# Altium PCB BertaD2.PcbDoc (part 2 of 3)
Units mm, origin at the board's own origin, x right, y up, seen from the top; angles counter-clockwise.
Board outline 100.5 x 100 mm, 4 copper layers (Top Layer, Signal Layer 1, Signal Layer 2, Bottom Layer), stack 0.778 mm thick; 108 components, 216 nets, 850 pads, 807 vias.
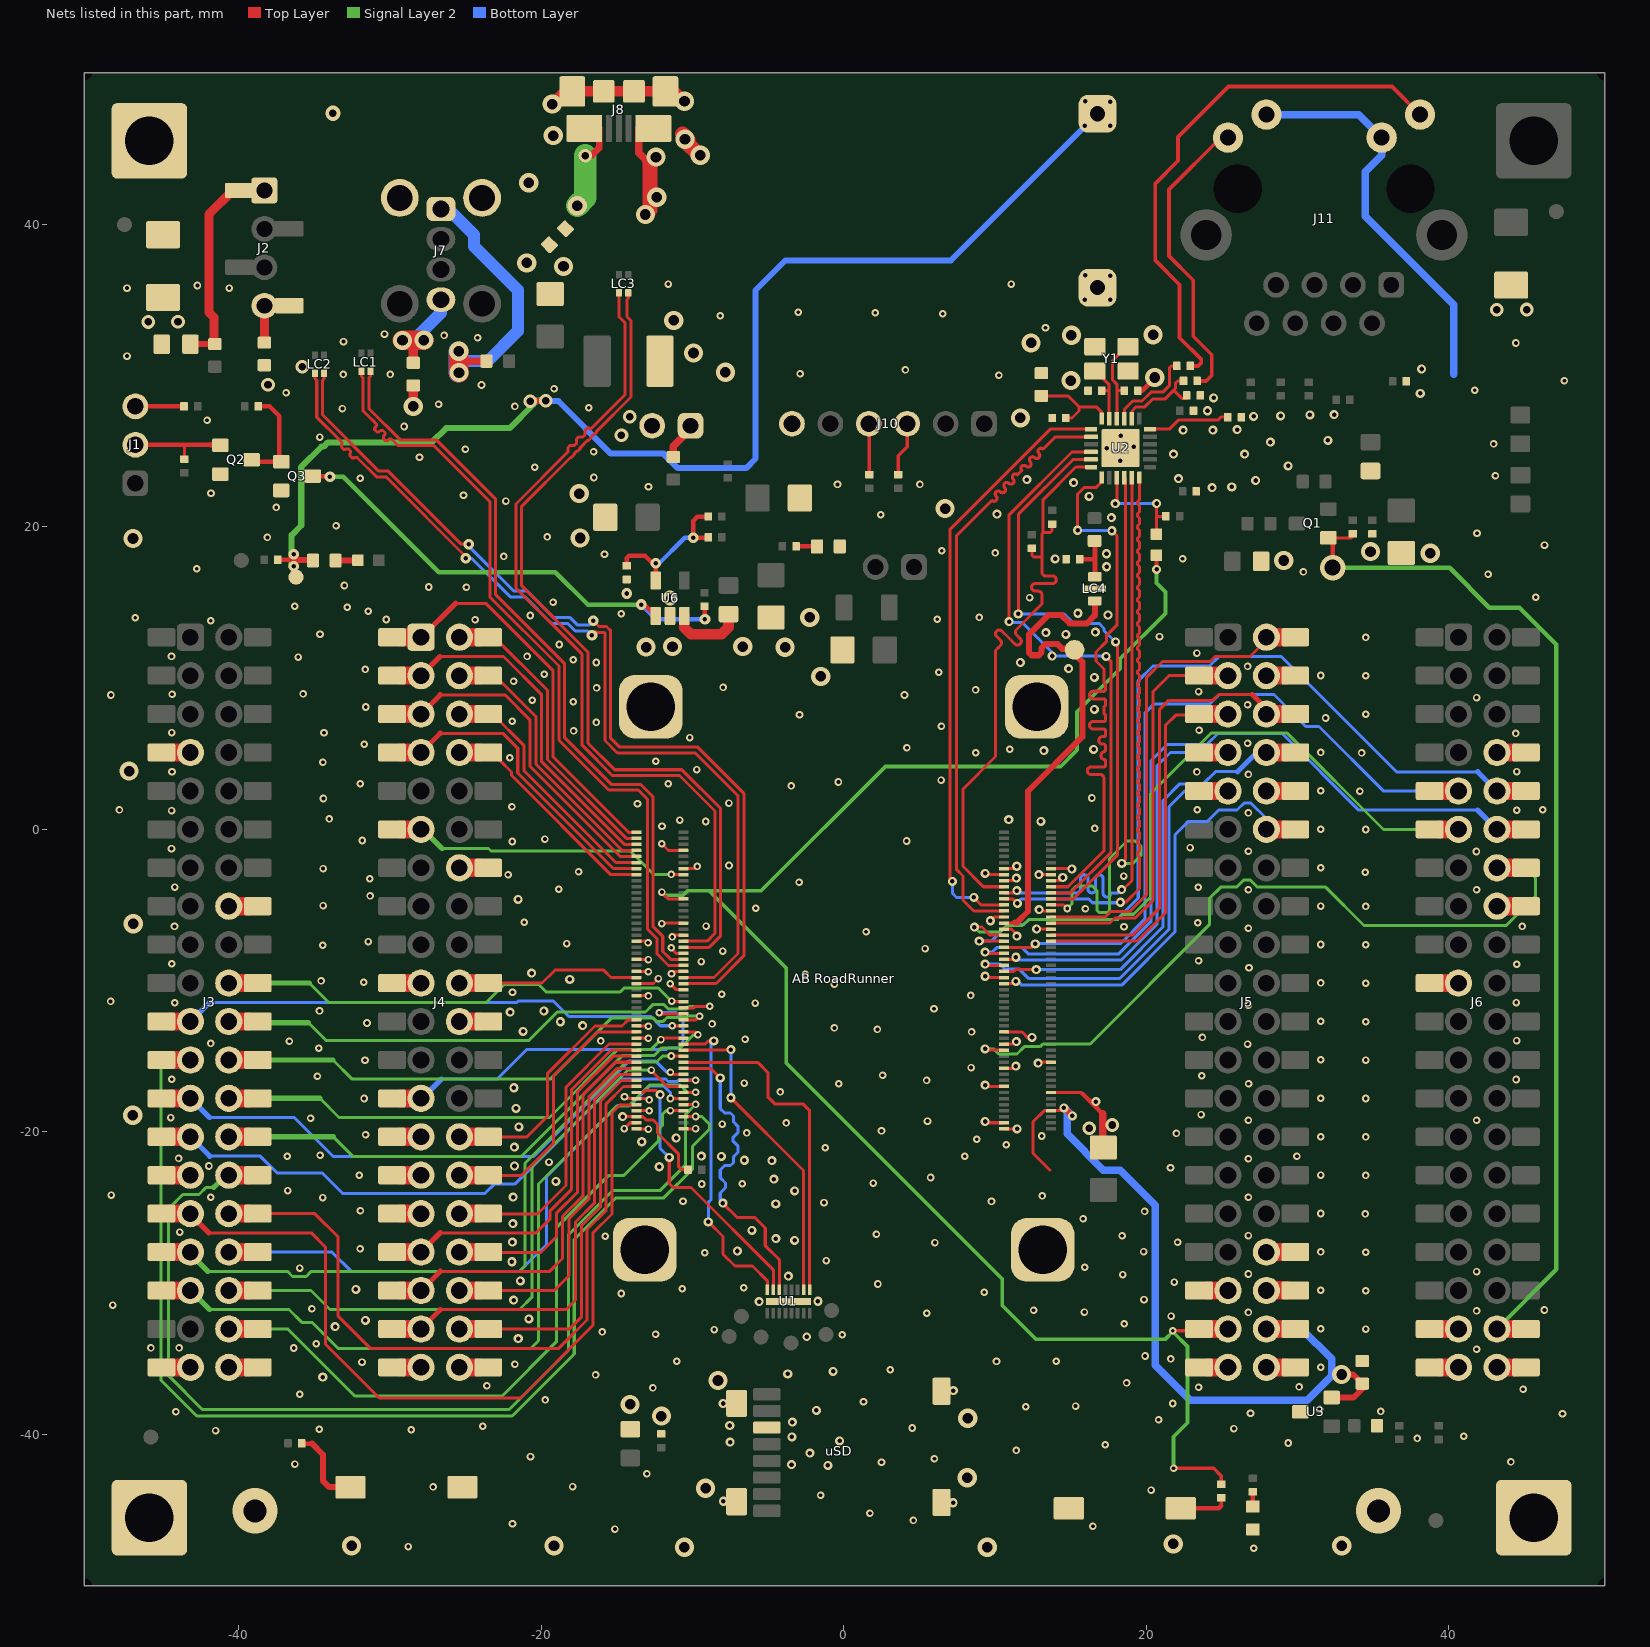
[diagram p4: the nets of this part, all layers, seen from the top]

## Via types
v1: diameter 0.5, hole 0.25, Top Layer to Bottom Layer, tented both sides, 469 vias
v2: diameter 0.6, hole 0.3, Top Layer to Bottom Layer, tented both sides, 200 vias
v3: diameter 1.27, hole 0.7, Top Layer to Bottom Layer, tented both sides, 72 vias
v4: diameter 0.7, hole 0.3, Top Layer to Bottom Layer, tented both sides, 20 vias
v5: diameter 0.9, hole 0.5, Top Layer to Bottom Layer, tented both sides, 19 vias
v6: diameter 0.7, hole 0.3, Top Layer to Bottom Layer, 8 vias
v7: diameter 1, hole 0.5, Top Layer to Bottom Layer, tented both sides, 6 vias
v8: diameter 1.7, hole 1.05, Top Layer to Bottom Layer, tented both sides, 5 vias
v9: diameter 3, hole 1.5, Top Layer to Bottom Layer, 3 vias
v10: diameter 1.7, hole 1.05, Top Layer to Bottom Layer, 3 vias
v11: diameter 0.56, hole 0.3, Top Layer to Bottom Layer, tented both sides, 1 vias
v12: diameter 0.8, hole 0.4, Top Layer to Bottom Layer, tented both sides, 1 vias

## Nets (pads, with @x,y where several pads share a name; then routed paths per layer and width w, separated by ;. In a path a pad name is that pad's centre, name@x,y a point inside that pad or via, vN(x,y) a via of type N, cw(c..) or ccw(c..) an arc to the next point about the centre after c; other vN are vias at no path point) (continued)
EARTH2: C6.2 J7.5 J7.6 J8.6 J8.7 J8.8 J8.9 J8.10 J8.11 pad.8@-45.892,45.508 | length 11.6
  Top Layer w0.7: v3(-19.26,47.94) -18.42,48.78 J8.10@-17.935,48.78 J8.9@-15.86,48.78 J8.8@-13.86,48.78 J8.7@-11.785,48.78 -11.17,48.78 v3(-10.52,48.13)
  Top Layer w1: v3@-10.653,45.968 -10.393,45.708 -10.295,45.61 v3(-10.49,45.61) -10.49,45.51 -9.54,44.56 v3(-9.48,44.56)
  other v3: -20.82,42.74 -19.2,45.86
  other v7: -33.76,47.33
ECK: C21.1 L9.1 LC4.1 | length 3.5
  Top Layer w0.3: C21.1@15.6,17.86 16.61,17.86 ; L9.1@16.54,19.12 16.585,19.075 16.61,19.05 16.61,17.86 ; LC4.1@16.57,16.71 16.58,16.72 16.61,16.75 16.61,17.86 ; 16.63,17.85 16.62,17.86 16.61,17.86
EN33: Q3.3 R4.2 U6.1 | length 32.1
  Top Layer w0.3: Q3.3@-35.232,23.353 -35.1,23.353 -33.999,23.353 v4(-33.957,23.311) ; v4(-13.376,14.862) -13.178,14.862 U6.1@-12.43,14.114 ; v4@-9.177,13.884 R4.2@-9.177,14.698
  Signal Layer 2 w0.3: v4(-33.957,23.311) -33.073,23.311 -26.76,16.998 -19.063,16.998 -16.927,14.862 v4(-13.376,14.862)
  Bottom Layer w0.3: v4(-13.376,14.862) -12.391,13.877 v4(-9.17,13.877)
ENABLE_ETH_N: J6.38 Q1.1 R11.2 | length 68.4
  Top Layer w0.2: Q1.1@32.32,18.98 Q1.1@32.03,19.27 33.55,19.27 33.65,19.37 R11.2@33.65,19.54
  Top Layer w0.3: v10@31.66,17.33 31.69,17.3 v10(32.32,17.3) Q1.1@32.32,18.98
  Signal Layer 2 w0.3: v10(32.32,17.3) 32.335,17.285 40.055,17.285 42.68,14.66 44.67,14.66 47.11,12.22 47.11,-29.09 J6.38@43.18,-33.02
ETH_CLK: "25 MHz.1" "AB RoadRunner.J2-31" LC4.2 | length 32
  Top Layer w0.2: 10.591,-6.191 10.595,-6.191 11.354,-6.19
  Top Layer w0.4: 11.327,-6.141 11.47,-6.141 12.18,-5.431 12.18,2.52 15.77,6.11 15.77,11.07 15.115,11.725 14.9,11.94 14.44,11.94 14.12,12.26 13.35,12.26 13.07,11.98 13.07,11.68 12.9,11.51 12.42,11.51 12.26,11.67 12.26,12.9 13.52,14.16 14.38,14.16 14.933,13.607 16.067,13.607 16.6,14.14 LC4.2@16.6,15.1
ETH_CRS: "AB RoadRunner.J2-24" U2.11 | length 39.8
  Top Layer w0.2: v2@11.54,14.28 11.54,20.82 15.17,24.45 U2.11@16.35,24.45 ; 13.705,-4.593 15.192,-4.593 18.112,-1.673 18.112,12.198 v2@17.96,12.35
  Bottom Layer w0.2: v2(11.54,14.24) 14.57,14.24 15.19,13.62 16.87,13.62 17.21,13.28 17.21,13.13 17.96,12.38 v2(17.97,12.39)
ETH_MDC: "AB RoadRunner.J2-20" U2.13 | length 40.1
  Top Layer w0.2: 13.705,-3.792 14.821,-3.792 17.2,-1.413 17.2,3.25 17.2,3.38 ccw(c16.95,3.38) 16.95,3.63 16.35,3.63 cw(c16.35,3.88) 16.1,3.88 cw(c16.35,3.88) 16.35,4.13 17.2,4.13 ccw(c17.2,4.232) 17.302,4.232 17.302,4.528 ccw(c17.2,4.528) 17.2,4.63 cw(c17.2,4.809) 17.021,4.809 17.021,4.951 cw(c17.2,4.951) 17.2,5.13 ccw(c17.2,5.232) 17.302,5.232 17.302,5.528 ccw(c17.2,5.528) 17.2,5.63 17.108,5.63 cw(c17.108,5.88) 16.858,5.88 cw(c17.108,5.88) 17.108,6.13 17.2,6.13 ccw(c17.2,6.232) 17.302,6.232 17.302,6.528 ccw(c17.2,6.528) 17.2,6.63 16.5,6.63 cw(c16.5,6.88) 16.25,6.88 cw(c16.5,6.88) 16.5,7.13 17.2,7.13 ccw(c17.2,7.232) 17.302,7.232 17.302,7.528 ccw(c17.2,7.528) 17.2,7.63 17.2,8.13 ccw(c17.2,8.232) 17.302,8.232 17.302,8.528 ccw(c17.2,8.528) 17.2,8.63 16.5,8.63 cw(c16.5,8.88) 16.25,8.88 cw(c16.5,8.88) 16.5,9.13 17.2,9.13 ccw(c17.2,9.232) 17.302,9.232 17.302,9.528 ccw(c17.2,9.528) 17.2,9.63 17.2,9.88 17.2,10.606 16.675,11.131 16.675,11.719 17.36,12.404 17.36,12.8 18.08,13.52 18.08,19.39 v2(17.73,19.74) ; v2(15.46,19.77) 15.46,22.16 15.912,22.612 16.702,22.612 17.05,22.96 U2.13@17.05,23.25
  Bottom Layer w0.2: v2(15.46,19.77) 17.7,19.77 v2(17.73,19.74)
ETH_MDIO: "AB RoadRunner.J2-19" R13.2 R14.2 U2.12 | length 41.4
  Top Layer w0.2: 10.595,-3.792 9.232,-3.792 7.885,-2.445 7.885,2.655 10.04,4.81 10.04,11.83 10.135,11.925 10.183,11.973 10.359,12.149 ccw(c10.183,12.326) 10.359,12.503 10.112,12.75 cw(c10.289,12.927) 10.112,13.104 cw(c10.289,12.927) 10.465,13.104 10.89,12.68 11.314,12.255 ccw(c11.491,12.432) 11.667,12.255 ccw(c11.491,12.432) 11.667,12.609 11.42,12.856 cw(c11.597,13.033) 11.42,13.21 13.1,14.89 13.1,15.49 13.1,15.5 ccw(c12.85,15.5) 12.85,15.75 12.672,15.75 cw(c12.672,16) 12.422,16 cw(c12.672,16) 12.672,16.25 13.1,16.25 13.8,16.25 ccw(c13.8,16.5) 14.05,16.5 ccw(c13.8,16.5) 13.8,16.75 13.35,16.75 cw(c13.35,17) 13.1,17 13.1,18 ; R13.2@12.44,18.57 12.44,18.12 12.56,18 13.1,18 ; 13.184,19.61 13.184,21.79 15.344,23.95 U2.12@16.35,23.95 ; R14.2@13.77,20.18 13.77,19.74 13.64,19.61 13.208,19.61 13.1,19.502 13.1,18
ETH_RX0: "AB RoadRunner.J2-27" U2.8 | length 41.4
  Top Layer w0.2: 10.595,-5.392 8.608,-5.392 8.6,-5.4 7.88,-4.68 7.88,-3.08 7.471,-2.671 7.471,19.421 9.69,21.64 9.792,21.742 ccw(c9.933,21.883) 10.074,21.742 ccw(c9.933,21.883) 10.074,22.024 cw(c10.216,22.166) 10.074,22.307 cw(c10.216,22.166) 10.357,22.307 ccw(c10.499,22.449) 10.64,22.307 ccw(c10.499,22.449) 10.64,22.59 cw(c10.782,22.732) 10.64,22.873 cw(c10.782,22.732) 10.923,22.873 ccw(c11.064,23.014) 11.206,22.873 ccw(c11.064,23.014) 11.206,23.156 cw(c11.347,23.297) 11.206,23.439 cw(c11.347,23.297) 11.489,23.439 11.772,23.722 cw(c11.913,23.863) 11.772,24.004 cw(c11.913,23.863) 12.054,24.004 ccw(c12.196,24.146) 12.337,24.004 ccw(c12.196,24.146) 12.337,24.287 cw(c12.479,24.429) 12.337,24.57 cw(c12.479,24.429) 12.62,24.57 ccw(c12.761,24.711) 12.903,24.57 ccw(c12.761,24.711) 12.903,24.853 cw(c13.044,24.994) 12.903,25.136 cw(c13.044,24.994) 13.186,25.136 13.469,25.419 13.61,25.56 14,25.95 U2.8@16.35,25.95
ETH_RX1: "AB RoadRunner.J2-25" U2.7 | length 39.9
  Top Layer w0.2: v2(7.19,-3.44) 7.038,-3.288 7.038,19.838 13.65,26.45 U2.7@16.35,26.45 ; v2(8.6,-4.5) 9.092,-4.992 10.595,-4.992
  Bottom Layer w0.2: v2(7.19,-3.44) 7.19,-4.23 7.46,-4.5 v2(8.6,-4.5)
ETH_RXER: "AB RoadRunner.J2-22" U2.10 | length 39.9
  Top Layer w0.2: v2(10.94,13.73) 10.94,20.8 15.09,24.95 U2.10@16.35,24.95 ; 13.705,-4.192 14.999,-4.192 17.682,-1.509 17.682,11.088 v2(17.34,11.43)
  Bottom Layer w0.2: v2(10.94,13.73) 11.01,13.66 11.82,13.66 13.77,11.71 v2(13.77,11.46) 17.31,11.46 v2(17.34,11.43)
ETH_TX0: "AB RoadRunner.J2-21" U2.17 | length 39.9
  Top Layer w0.2: 10.595,-4.192 11.308,-4.192 v2(11.45,-4.05) ; v2(18.37,-3.98) 18.457,-3.98 19.05,-3.387 U2.17@19.05,23.25
  Bottom Layer w0.2: v2(11.45,-4.05) 11.6,-4.2 14.92,-4.2 15.15,-4.2 15.4,-4.2 ccw(c15.4,-3.95) 15.65,-3.95 15.65,-3.25 cw(c15.9,-3.25) 15.9,-3 cw(c15.9,-3.25) 16.15,-3.25 16.15,-3.95 ccw(c16.4,-3.95) 16.4,-4.2 ccw(c16.4,-3.95) 16.65,-3.95 16.65,-3.25 cw(c16.9,-3.25) 16.9,-3 cw(c16.9,-3.25) 17.15,-3.25 17.15,-4.2 17.15,-4.22 ccw(c17.4,-4.22) 17.4,-4.47 ccw(c17.4,-4.22) 17.65,-4.22 cw(c17.67,-4.22) 17.67,-4.2 17.9,-4.2 18.15,-4.2 v2(18.37,-3.98)
ETH_TX1: "AB RoadRunner.J2-23" U2.18 | length 39.8
  Top Layer w0.2: 10.595,-4.593 11.172,-4.593 v2@11.43,-4.85 ; v2(18.288,-4.815) 18.645,-4.815 19.55,-3.91 19.55,-2.4 19.55,-2.22 19.55,-1.82 19.43,-1.7 19.43,-1.54 19.55,-1.42 19.55,-1.02 19.43,-0.9 19.43,-0.74 19.55,-0.62 19.55,-0.22 19.43,-0.1 19.43,0.06 19.55,0.18 19.55,0.58 19.43,0.7 19.43,0.86 19.55,0.98 19.55,1.38 19.43,1.5 19.43,1.66 19.55,1.78 19.55,2.18 19.43,2.3 19.43,2.46 19.55,2.58 19.55,2.98 19.43,3.1 19.43,3.26 19.55,3.38 19.55,3.78 19.43,3.9 19.43,4.06 19.55,4.18 19.55,4.58 19.43,4.7 19.43,4.86 19.55,4.98 19.55,5.38 19.43,5.5 19.43,5.66 19.55,5.78 19.55,6.18 19.43,6.3 19.43,6.46 19.55,6.58 19.55,6.98 19.43,7.1 19.43,7.26 19.55,7.38 19.55,7.78 19.43,7.9 19.43,8.06 19.55,8.18 19.55,8.58 19.43,8.7 19.43,8.86 19.55,8.98 19.55,9.38 19.43,9.5 19.43,9.66 19.55,9.78 19.55,10.18 19.43,10.3 19.43,10.46 19.55,10.58 19.55,10.98 19.43,11.1 19.43,11.26 19.55,11.38 19.55,11.78 19.43,11.9 19.43,12.06 19.55,12.18 19.55,12.58 19.43,12.7 19.43,12.86 19.55,12.98 19.55,13.38 19.43,13.5 19.43,13.66 19.55,13.78 19.55,14.18 19.43,14.3 19.43,14.46 19.55,14.58 19.55,14.98 19.43,15.1 19.43,15.26 19.55,15.38 19.55,15.78 19.43,15.9 19.43,16.06 19.55,16.18 19.55,16.58 19.43,16.7 19.43,16.86 19.55,16.98 19.55,17.38 19.43,17.5 19.43,17.66 19.55,17.78 19.55,18.18 19.43,18.3 19.43,18.46 19.55,18.58 19.55,18.98 19.43,19.1 19.43,19.26 19.55,19.38 19.55,19.78 19.43,19.9 19.43,20.06 19.55,20.18 19.55,20.58 19.43,20.7 19.43,20.86 19.55,20.98 19.55,21.38 19.43,21.5 19.43,21.66 19.55,21.78 19.55,22.18 19.55,22.38 U2.18@19.55,23.25
  Bottom Layer w0.2: v2(11.477,-4.896) 11.477,-4.867 11.498,-4.846 11.476,-4.824 11.67,-4.63 11.69,-4.63 11.72,-4.6 16.195,-4.6 16.445,-4.85 18.26,-4.85 18.288,-4.822 v2(18.288,-4.815)
ETH_TXEN: "AB RoadRunner.J2-26" U2.16 | length 40.5
  Top Layer w0.2: 13.705,-4.992 14.543,-4.992 v1(14.78,-5.23) ; v2(18.38,-2.25) 18.625,-2.005 18.625,23.175 U2.16@18.55,23.25
  Signal Layer 2 w0.2: v1(14.78,-5.23) 15.09,-4.92 15.09,-4.03 15.38,-3.74 16.43,-3.74 16.74,-4.05 16.74,-5.35 16.87,-5.48 17.45,-5.48 17.57,-5.36 17.57,-1.92 18.72,-0.77 19.28,-0.77 19.66,-1.15 19.66,-1.69 19.1,-2.25 v2(18.38,-2.25)
ETHLED1: J11.9 R20.2 | length 35.8
  Top Layer w0.25: R20.2@22.92,30.63 23.41,30.63 23.64,30.86 23.64,31.06 22.2,32.5 22.2,36 20.6,37.6 20.6,42.7 22.1,44.2 22.1,45.763 25.437,49.1 36.24,49.1 J11.9@38.1,47.24
ETHLED2: J11.12 R21.2 | length 19.9
  Top Layer w0.25: R21.2@23.36,29.64 23.97,29.64 24.33,30 24.33,31.37 23.1,32.6 23.1,36.3 21.5,37.9 21.5,42.3 24.92,45.72 J11.12@25.4,45.72
FUSE2V5: "AB RoadRunner.J2-94" C27.1 J5.38 U3.2 | length 51.5
  Top Layer w0.2: 13.64,-22.53 12.513,-21.403 12.513,-19.328 13.248,-18.593 13.705,-18.593 14.554,-18.593 14.773,-18.593 14.81,-18.593 ; v2@14.526,-18.404 v2(14.554,-18.404)
  Top Layer w0.4: v2(14.554,-18.404) 14.584,-18.404 14.773,-18.593 v2(15.12,-18.94) ; U3.2@32.25,-37.55 33.7,-37.55 34.28,-36.97 C27.1@34.28,-36.64 33.67,-36.03 v3(32.91,-36.03)
  Bottom Layer w0.5: v2(14.554,-18.404) 14.584,-18.404 v2@14.77,-18.59 ; v2(15.12,-18.94) v2@14.77,-18.59 ; J5.38@27.94,-33.032 30.292,-33.032 32.25,-34.99 32.25,-36.03 32.25,-36.12 30.63,-37.74 22.92,-37.74 20.6,-35.42 20.6,-24.86 18.27,-22.53 17.17,-22.53 14.77,-20.13 14.77,-18.94 v2@14.77,-18.59
GND: "AB RoadRunner.J1-8" "AB RoadRunner.J1-14" "AB RoadRunner.J1-32" "AB RoadRunner.J1-36" "AB RoadRunner.J1-37" "AB RoadRunner.J1-42" "AB RoadRunner.J1-43" "AB RoadRunner.J1-47" "AB RoadRunner.J1-48" "AB RoadRunner.J1-51" "AB RoadRunner.J1-54" "AB RoadRunner.J1-55" "AB RoadRunner.J1-65" "AB RoadRunner.J1-69" "AB RoadRunner.J1-89" "AB RoadRunner.J1-93" "AB RoadRunner.J1-97" "AB RoadRunner.J1-99" "AB RoadRunner.J1-100" "AB RoadRunner.J1-101" "AB RoadRunner.J1-102" "AB RoadRunner.J2-13" "AB RoadRunner.J2-14" "AB RoadRunner.J2-15" "AB RoadRunner.J2-16" "AB RoadRunner.J2-17" "AB RoadRunner.J2-18" "AB RoadRunner.J2-28" "AB RoadRunner.J2-29" "AB RoadRunner.J2-33" "AB RoadRunner.J2-34" "AB RoadRunner.J2-49" "AB RoadRunner.J2-67" "AB RoadRunner.J2-71" "AB RoadRunner.J2-78" "AB RoadRunner.J2-79" "AB RoadRunner.J2-85" "AB RoadRunner.J2-88" "AB RoadRunner.J2-97" "AB RoadRunner.J2-99" "AB RoadRunner.J2-101" "AB RoadRunner.J2-102" C1.2 C2.2 C3.2 C4.2 C6.1 C7.2 C8.2 C9.1 C10.2 C11.2 C12.2 C13.2 C14.2 C15.1 C16.1 C17.2 C18.2 C19.2 C20.2 C21.2 C22.2 C23.2 C24.2 C25.2 C26.1 C27.2 DL1.K DL2.K J3.7 J3.16 J3.29 J3.39 J3.40 J4.14 J4.19 J4.22 J4.29 J4.39 J4.40 J5.4 J5.10 J5.36 J5.39 J5.40 J6.8 J6.16 J6.19 J6.39 J6.40 J9.2 J10.6 J11.10 J11.11 L4.1 L5.1 L6.1 LC4.3 P1.1 P2.1 pad.8@45.608,-45.492 pad.8@-45.892,-45.492 Q2.2 Q3.2 R5.2 R22.1 R23.2 U1.17 U2.25 U3.3 U6.2 uSD.6 uSD.9 uSD.10 uSD.11 uSD.12 Y1.2 Y1.4 | length 80.6
  Top Layer w0.2: J4.22@-25.59,-12.85 -25.42,-12.68 J4.22@-25.37,-12.63 ; v1(-14.5,-19.775) -14.117,-19.392 -13.705,-19.392 ; v1(-14.49,-17.68) -14.377,-17.792 -13.705,-17.792 v1@-12.852,-17.792 ; -13.928,-10.192 -13.705,-10.192 -12.572,-10.192 v1(-12.244,-9.864) ; -13.888,-10.993 -13.705,-10.993 v1@-12.91,-10.993 ; -13.705,-19.793 -12.91,-19.793 v1@-12.852,-19.793 ; -13.705,-18.593 v1(-12.852,-18.593) ; -13.705,-13.792 -12.91,-13.792 v1@-12.852,-13.792 ; -13.705,-12.992 -12.91,-12.992 v1@-12.852,-12.992 ; -13.705,-9.393 -12.91,-9.393 v1@-12.852,-9.393 ; -13.705,-8.592 -12.91,-8.592 v1@-12.852,-8.592 ; -13.705,-7.392 -12.93,-7.392 v1@-12.852,-7.392 ; v1@-12.03,-6.192 -12.021,-6.192 -10.595,-6.192 ; v1(-12.02,-0.95) -11.578,-1.392 -10.595,-1.392 ; v1(-11.47,-10.2) -11.46,-10.2 -11.068,-10.592 ; v1@-11.447,-9.393 -11.38,-9.393 -10.595,-9.393 ; v1(-11.403,-7.829) -11.403,-7.877 -11.087,-8.193 ; v1(-11.334,-7.106) -11.326,-7.106 v1@-11.212,-6.993 ; v1@-11.209,-6.993 -10.595,-6.993 ; -11.045,-10.592 -10.595,-10.592 ; -11.045,-8.193 -10.595,-8.193 ; -10.595,-19.793 -9.79,-19.793 v1@-9.742,-19.793 ; -10.595,-2.592 v1@-9.742,-2.592 ; v2(9.35,-19.31) 9.432,-19.392 10.595,-19.392 ; v2(9.35,-16.91) 9.432,-16.993 10.595,-16.993 ; v2(9.35,-9.71) 9.432,-9.793 10.595,-9.793 ; v2(9.35,-2.91) 9.432,-2.992 10.595,-2.992 ; v2(9.697,-6.038) 9.944,-5.791 10.593,-5.791 ; 10.595,-19.793 11.459,-19.793 11.519,-19.793 11.517,-19.794 v2(11.459,-19.794) ; 10.595,-15.793 11.238,-15.793 v2(11.38,-15.65) ; 10.595,-14.193 v2@11.238,-14.193 ; 10.595,-3.393 11.258,-3.393 11.414,-3.236 v2(11.414,-3.225) ; 10.595,-2.592 11.388,-2.592 11.44,-2.54 v2(11.44,-2.436) ; 10.629,-13.394 11.794,-13.394 v2@12.2,-13.8 ; 10.629,-6.593 11.093,-6.593 v2@11.47,-6.97 ; v2@12.75,-15.391 12.856,-15.391 13.705,-15.391 ; v2(12.75,-6.585) 12.757,-6.592 13.705,-6.592 ; v2@12.902,-2.992 13.705,-2.992 ; v2@12.992,-5.392 13.705,-5.392 ; 13.705,-17.392 15.713,-17.392 ; 13.705,-3.393 14.268,-3.393 v2(14.48,-3.18) ; 13.705,-2.592 v2@15.08,-2.592
  Top Layer w0.25: C10.2@17.13,-20.99 C10.2@17.17,-21.03
  Top Layer w0.3: 15.818,-17.498 16.495,-18.175 17.13,-18.81 ; C20.2@19.45,29 19.731,29 20.56,29.829 v3(20.56,29.87)
  Top Layer w0.5: C10.2@17.13,-20.99 17.13,-19.54 17.13,-18.81
  Top Layer w0.6: v3(-28.45,27.96) L4.1@-28.45,29.34 ; v6(15.946,35.007) 15.982,35.007 C7.2@16.78,35.805 ; v6(15.978,36.633) 15.978,36.607 C7.2@16.78,35.805 ; v6(17.604,35.007) 17.578,35.007 C7.2@16.78,35.805 ; v6(17.604,36.601) 17.576,36.601 C7.2@16.78,35.805
  Top Layer w1.2: J5.36@27.94,-30.48 27.958,-30.462 29.222,-30.462 J5.36@29.24,-30.48
  Bottom Layer w0.5: J11.11@27.94,47.24 34.04,47.24 J11.10@35.56,45.72 35.56,44.55 34.48,43.47 34.48,40.54 40.33,34.69 40.33,30.08
  other v1: 27.11,-47.52 -28.78,-47.41 -15.12,-46.25 16.47,-46.06 -21.89,-45.89 4.61,-45.68 1.73,-45.21 -1.53,-44.02 20.32,-43.67 -27.14,-43.46 -17.92,-43.44 -13.01,-42.59 -36.27,-41.95 2.5,-41.83 44.1,-41.81 6,-41.6 -20.7,-41.46 11.4,-41.05 17.29,-40.67 29.38,-40.56 37.91,-40.26 40.99,-40.11 -41.52,-39.74 -28.58,-39.69 -34.67,-39.65 25.793,-39.61 4.53,-39.57 -23.86,-39.45 20.813,-39.029 47.51,-38.63 26.89,-38.59 -44.142,-38.497 35.5,-38.47 31.46,-38.32 12.04,-38.16 15.33,-38.12 21.75,-37.95 1.31,-37.83 -19.73,-37.71 -35.95,-37.34 44.904,-37 -12.61,-36.92 23.46,-36.87 30.1,-36.85 -23.58,-36.77 18.7,-36.59 -16.4,-36.06 3.08,-35.72 31.53,-35.55 -21.73,-35.358 -31.84,-35.21 -11.03,-35.16 10.1,-35.17 14.05,-35.15 21.62,-35 19.92,-34.81 41.83,-34.36 -45.793,-34.272 -43.929,-34.274 -36.35,-34.28 -34.87,-34 -0.1,-33.4 -12.43,-33.37 -15.96,-33.22 -8.55,-33.06 34.51,-33.03 31.53,-33.01 18.54,-32.68 21.64,-32.17 5.49,-31.98 26.75,-31.93 15.91,-31.91 41.83,-31.83 12.55,-31.78 46.319,-31.767 -35.149,-31.682 -48.309,-31.441 19.85,-31.08 -14.7,-30.68 9.29,-30.6 34.51,-30.49 31.53,-30.47 -10.67,-30.36 -6.61,-30.3 2.26,-30.05 21.85,-29.92 18.44,-29.43 26.75,-29.39 41.83,-29.23 -35.96,-29 15.94,-28.95 -1.16,-28.5 -9.19,-27.98 34.51,-27.95 19.82,-27.91 31.53,-27.93 -31.962,-27.722 6.03,-27.31 22.07,-27.29 -15.76,-26.9 18.4,-26.86 26.75,-26.85 2.16,-26.76 -43.89,-26.62 15.82,-25.74 34.48,-25.416 31.53,-25.39 19.89,-25.25 -31.943,-25.213 -1.3,-24.67 -10.62,-24.58 9.77,-24.59 -34.43,-24.34 -41.83,-24.31 26.75,-24.31 13.12,-24.23 -48.406,-24.173 -36.744,-23.878 -9.38,-23.44 -6.7,-23.43 1.95,-23.38 5.74,-23.01 -32.02,-22.86 34.51,-22.87 31.53,-22.85 21.6,-22.37 -41.96,-22.25 -19.48,-21.99 26.75,-21.77 -43.96,-21.75 -36.78,-21.61 8,-21.61 29.96,-21.61 -34.61,-21.54 -1.22,-21.04 10.75,-20.841 8.8,-20.48 34.51,-20.33 31.53,-20.31 13.093,-20.269 -31.6,-20.19 21.99,-20.1 -6.41,-20.06 2.5,-19.93 -12.91,-19.81 -9.79,-19.78 -8.03,-19.48 -3.8,-19.4 5.54,-19.28 26.75,-19.23 41.83,-19.23 -35.24,-19.09 -44.483,-19.054 23.62,-18.85 -12.852,-17.883 -31.7,-17.79 34.51,-17.79 31.53,-17.77 -4.2,-17.35 -0.32,-16.82 26.764,-16.811 -6.57,-16.77 5.48,-16.59 44.443,-16.532 -44.414,-16.523 -34.785,-16.325 23.66,-16.289 2.57,-16.25 8.421,-15.744 -31.64,-15.26 34.51,-15.25 31.53,-15.23 -34.7,-14.47 26.7,-14.19 -41.83,-14.15 -36.64,-14.01 -16.06,-13.98 44.474,-13.962 -6.519,-13.867 -12.91,-13.81 23.71,-13.75 8.45,-13.386 2.23,-13.22 -0.61,-13.12 -12.91,-13.01 -8.7,-12.862 -31.51,-12.8 34.51,-12.71 31.53,-12.69 -34.65,-12 5.97,-11.86 26.75,-11.61 -5.85,-11.48 -44.216,-11.457 44.451,-11.447 -48.454,-11.371 -12.91,-11.01 8.398,-10.972 -8.053,-10.891 -21.89,-10.77 -0.61,-10.22 34.51,-10.17 31.53,-10.15 -31.73,-10.1 -34.54,-10.02 -2.54,-9.58 -11.38,-9.542 -12.91,-9.41 26.791,-9.149 44.487,-8.915 -44.418,-8.884 -9.41,-8.74 23.46,-8.69 -12.91,-8.61 -7.994,-8.048 5.38,-7.88 -34.44,-7.66 34.51,-7.63 31.53,-7.61 -18.3,-7.55 -12.93,-7.487 -31.42,-7.42 1.48,-6.76 26.75,-6.53 18.529,-6.439 -44.234,-6.416 44.845,-6.411 -9.093,-6.391 -12.021,-6.23 23.4,-6.17 -21.11,-6.14 15.98,-5.24 -5.81,-5.21 34.51,-5.09 31.53,-5.07 -34.41,-5.04 -31.308,-4.396 26.75,-3.99 41.83,-3.99 -18.841,-3.962 23.43,-3.83 -44.221,-3.813 -2.95,-3.5 -31.323,-3.259 18.51,-3.09 -22.184,-3.001 34.479,-2.836 -17.524,-2.808 -34.41,-2.59 31.53,-2.53 -9.68,-2.45 -7.58,-2.39 26.75,-1.45 41.818,-1.462 -44.43,-1.268 22.896,-1.203 -21.907,-0.803 4.16,-0.77 -31.821,-0.734 -19.752,-0.642 34.51,-0.01 31.53,0.01 16.599,0.066 -12.01,0.21 -9.118,0.519 -10.842,0.613 -34.003,0.688 26.75,1.09 -44.428,1.243 44.485,1.269 -47.873,1.289 23.37,1.29 46.207,1.29 -21.928,1.494 -13.63,1.69 -7.59,1.74 -34.39,2.04 16.406,2.075 34.12,2.52 31.53,2.55 -3.46,2.87 -31.95,3.01 -11.6,3.01 -0.35,3.13 6.44,3.26 26.75,3.63 -44.396,3.812 23.35,3.8 44.49,3.819 -9.71,3.95 -34.42,4.43 -12.426,4.5 -22.077,4.741 8.73,5.06 34.233,5.053 31.53,5.09 10.97,5.3 4.18,5.4 -31.69,5.63 26.7,5.69 -10.17,6.07 44.427,6.344 -34.35,6.38 -44.416,6.394 -17.851,6.506 23.492,6.557 6.46,6.81 -16.36,7.07 -21.91,7.15 31.85,7.36 -2.92,7.57 34.51,7.61 -31.59,8.09 26.7,8.23 -17.87,8.44 -20.59,8.54 41.83,8.71 -48.437,8.882 4.02,8.88 -44.395,8.925 -35.73,8.95 23.46,9.11 8.72,9.22 -16.33,9.35 -7.97,9.38 -21.82,9.79 34.51,10.15 31.53,10.17 -19.79,10.26 6.28,10.39 -31.62,10.57 26.7,10.77 -16.35,11.03 -17.87,11.21 -36.05,11.39 -44.431,11.429 -20.93,11.43 23.344,11.649 -18.8,12.22 34.51,12.69 20.875,12.744 -34.616,12.899 -41.83,13.79 -30.24,13.871 -24.361,13.858 6.18,13.89 -46.82,13.99 8.96,14.01 -20.713,14.138 -14.7,14.25 -31.43,14.42 -32.81,14.68 -36.28,14.75 -19.21,15.016 12.29,15.32 45.746,15.338 -27.43,16.02 -24.94,16.01 -33,16.12 42.59,16.87 30.39,17.02 -42.76,17.22 22.4,17.89 -22.466,18.04 -15.81,18.18 10.02,18.27 6.48,18.41 46.32,18.79 -38.09,19.3 -19.59,19.33 41.86,19.57 -33.55,20.07 2.45,20.79 -37.51,21.28 -22.33,21.7 -25.13,22.09 -41.818,22.218 -12.9,22.64 -0.41,22.8 5.04,22.8 -31.95,23.21 -16.51,23.26 43.08,23.38 -20.42,23.94 -28.04,24.6 -16.53,24.96 -25,25.13 42.96,25.48 -34.63,25.93 -29.06,26.63 -42.081,27.04 -33.13,27.81 -16.85,27.87 -21.73,27.96 -26.78,28.1 -36.86,28.86 41.71,29.03 -19.14,29.12 -23.94,29.37 47.64,29.66 10.26,30.01 -33.08,30.07 -29.97,30.07 -2.88,30.11 4.08,30.37 -47.37,31.28 44.43,32.15 -33.06,32.24 -24.2,32.49 -26.41,32.65 -30.35,32.74 13.341,33.157 -8.16,33.95 6.55,34.08 2.08,34.15 -3.01,34.18 -47.37,35.78 -40.62,35.78 -42.72,35.95 -11.59,36.04 11.08,36.04
  other v2: 7.23,-44.51 -7.95,-44.41 -1.04,-42.04 -3.45,-41.99 -2.23,-41.23 -7.501,-40.498 -0.27,-40.42 -3.42,-40.15 -7.529,-39.403 -3.39,-39.18 -1.81,-38.41 -7.97,-37.95 7.24,-37.1 -34.432,-36.209 -3.7,-35.99 -0.7,-35.82 -21.511,-33.656 -33.615,-32.862 -31.61,-32.46 -20.81,-32.36 -5.59,-31.21 -1.71,-31.19 -21.82,-31.12 -32.238,-30.403 -21.37,-29.85 -3.651,-29.53 -21.93,-28.58 -7.03,-27.87 -21.894,-27.279 -3.25,-27.17 -4.48,-27.05 -6.07,-26.5 -21.86,-26.06 -4.49,-24.76 -21.85,-24.31 -3.25,-23.9 -19.027,-23.27 -4.62,-23.12 -12.19,-22.3 -21.76,-22.25 -4.75,-21.89 -6.56,-21.87 -8.08,-21.62 -9.4,-21.6 -21.77,-21 -13.346,-20.647 -11.082,-20.401 -21.464,-19.668 -21.66,-18.44 16.67,-18 -21.8,-17.08 12.856,-15.445 11.411,-14.031 12.447,-13.755 -21.19,-13.347 -17.26,-12.97 -18.721,-12.716 -22.053,-12.084 -19.82,-12.005 -18.108,-9.91 -20.628,-9.507 11.45,-7.05 12.92,-5.31 -21.52,-4.63 12.9,-2.99 15.08,-2.62 13.03,0.53 10.91,0.65 13.234,5.203 16.522,5.292 16.57,7.933 16.567,10.046 14.87,10.63 11.68,11.03 14.69,12.89 13.37,13.01 16.63,13.04 17.47,14.17 15.485,14.287 17.38,17.36 13.98,17.88 17.37,18.22 17.69,20.61 10.134,20.837 16.225,22.013 24.353,22.583 25.65,22.64 15.195,22.919 27.23,23.06 12.11,23.12 22.13,23.19 29.38,24.03 21.8,24.8 26.5,24.8 28.2,25.6 32.01,25.71 22.43,26.39 24.4,26.39 26.007,26.424 27.09,27.3 28.88,27.33 30.82,27.4 32.42,27.41 24.047,27.672 24.45,28.52 38.11,28.82 38.2,30.43
  other v3: -10.53,-47.45 9.49,-47.45 -32.529,-47.356 -19.151,-47.356 32.917,-47.356 21.78,-47.23 -9.13,-43.55 8.16,-42.85 8.2,-38.92 -12.05,-38.78 -14.12,-38.01 -8.31,-36.43 -46.995,-18.897 -46.965,-6.237 -47.231,3.852 -1.52,10.11 -3.873,12.038 -13.059,12.051 -11.318,12.079 -6.678,12.08 -2.25,14.01 29.09,17.77 38.77,18.25 34.82,18.36 -46.975,19.228 -17.422,19.261 6.7,21.2 -17.482,22.196 11.68,27.2 15.02,29.66 12.387,32.155 15.05,32.66 20.45,32.7 -18.52,37.21 -20.955,37.441
  other v4: -14.333,15.59 18.271,24.359 17.401,25.201 19.169,25.304 18.317,26.025
  other v5: 16.24,-19.75 17.74,-19.54 -14.69,26.04 -14.15,27.27 -38.05,29.39 -35.78,30.57 -45.97,33.54 -44,33.55 43.17,34.35 45.14,34.36
  other v7: -11.48,15.286
  other v9: -38.91,-45.048 35.351,-45.048
  other v11: -2.44,-33.539
HHSDA_N: "AB RoadRunner.J1-40" LC3.4 | length 56.6
  Top Layer w0.2: LC3.4@-14.24,35.46 -14.24,35.11 -14.329,35.021 -14.329,33.891 -14.06,33.623 -14.06,28.58 -16.324,26.316 -16.324,26.258 -16.488,26.094 -16.546,26.094 -16.707,25.933 -16.707,25.875 -16.871,25.711 -16.929,25.711 -17.414,25.226 -17.414,25.168 -17.578,25.004 -17.636,25.004 -17.838,24.802 -17.838,24.743 -18.002,24.579 -18.061,24.579 -21.286,21.354 -21.286,16.104 -16.91,11.728 -16.91,5.71 -15.14,3.94 -10.697,3.94 -8.13,1.373 -8.13,-7.033 -8.89,-7.792 -10.595,-7.792
HHSDA_P: "AB RoadRunner.J1-38" LC3.1 | length 56.4
  Top Layer w0.2: LC3.1@-14.84,35.46 -14.84,33.865 -14.44,33.465 -14.44,28.737 -16.704,26.474 -16.762,26.474 -16.804,26.515 -16.945,26.515 -17.087,26.374 -17.087,26.232 -17.087,26.091 -17.228,25.949 -17.369,25.949 -17.511,25.949 -17.652,25.808 -17.652,25.667 -17.652,25.525 -17.794,25.384 -17.935,25.384 -18.077,25.384 -18.218,25.242 -18.218,25.101 -18.218,24.959 -18.289,24.889 -21.666,21.511 -21.666,15.947 -17.29,11.571 -17.29,5.553 -15.297,3.56 -10.855,3.56 -8.51,1.215 -8.51,-6.875 -9.027,-7.392 -10.595,-7.392
HHSDB_N: "AB RoadRunner.J1-46" LC1.1 | length 52.2
  Top Layer w0.2: LC1.1@-31.88,30.28 -31.88,29.93 -31.865,29.93 -31.765,29.83 -31.765,27.698 -31.78,27.683 -31.304,27.206 -31.101,27.004 -30.889,26.792 -30.889,26.651 -30.995,26.544 -30.995,26.403 -30.854,26.262 -30.713,26.262 -30.607,26.368 -30.465,26.368 -30.324,26.226 -30.324,26.085 -30.43,25.979 -30.43,25.837 -30.288,25.696 -30.147,25.696 -30.041,25.802 -29.899,25.802 -29.829,25.731 -29.467,25.37 -27.087,25.37 -23.386,21.669 -23.386,15.359 -18.82,10.793 -18.82,5.897 -15.523,2.6 -13.587,2.6 -12.97,1.983 -12.97,-6.597 -12.34,-7.227 -12.34,-8.227 -11.575,-8.992 -10.712,-8.992 ; -10.732,-8.972 -10.712,-8.992 ; -10.595,-8.992 -10.712,-8.992
HHSDB_P: "AB RoadRunner.J1-44" LC1.4 | length 50.6
  Top Layer w0.2: LC1.4@-31.28,30.28 -31.28,29.93 -31.285,29.93 -31.385,29.83 -31.385,27.825 -29.31,25.75 -26.93,25.75 -23.006,21.826 -23.006,15.516 -18.44,10.95 -18.44,6.055 -15.365,2.98 -13.43,2.98 -12.59,2.14 -12.59,-6.44 -11.96,-7.07 -11.96,-8.07 -11.438,-8.592 -10.595,-8.592
HHSDC_N: "AB RoadRunner.J1-52" LC2.4 | length 61
  Top Layer w0.2: LC2.4@-34.34,30.14 -34.34,29.79 -34.45,29.68 -34.45,27.405 -30.725,23.68 -30.102,23.68 -25.272,18.85 v4(-24.782,18.85) v4@-24.713,18.85 ; v4(-16.552,13.781) -16.178,13.407 -15.674,13.407 -15.4,13.133 -15.4,6.025 -14.805,5.43 -9.647,5.43 -6.6,2.383 -6.6,-8.363 -8.43,-10.192 -10.595,-10.192
  Bottom Layer w0.2: v4(-24.782,18.85) -24.782,18.723 -21.809,15.75 -20.921,15.75 -19.163,13.991 -18.079,13.991 -17.581,13.493 -16.84,13.493 v4(-16.552,13.781)
HHSDC_P: "AB RoadRunner.J1-50" LC2.1 | length 61
  Top Layer w0.2: LC2.1@-34.94,30.14 -34.94,29.79 -34.83,29.68 -34.83,27.247 -33.281,25.699 -33.162,25.579 -33.162,25.438 -33.197,25.402 -33.197,25.261 -33.056,25.12 -32.915,25.12 -32.879,25.155 -32.738,25.155 -32.596,25.014 -32.596,24.872 -32.632,24.837 -32.632,24.695 -32.49,24.554 -32.349,24.554 -32.314,24.589 -32.172,24.589 -32.101,24.519 -30.883,23.3 -30.259,23.3 -24.932,17.972 -24.87,17.911 v4(-24.994,17.91) ; v4(-16.639,12.833) -16.609,12.833 -16.375,13.067 -16.335,13.027 -15.831,13.027 -15.78,12.976 -15.78,5.867 -14.963,5.05 -9.805,5.05 -6.98,2.225 -6.98,-8.205 -8.567,-9.793 -10.595,-9.793
  Bottom Layer w0.2: v4(-24.994,17.91) -24.578,17.91 -22.038,15.37 -21.079,15.37 -19.32,13.611 -18.237,13.611 -17.738,13.113 -16.919,13.113 v4(-16.639,12.833)
IN_5V: F1.1 J8.1 J9.1 L3.2 | length 8
  Top Layer w0.5: J8.1@-13.56,46.33 -13.56,44.73 -12.838,44.008 v3@-12.81,43.98 ; v3(-13.11,40.641) v3@-12.81,40.94 ; L3.2@-11.26,24.89 -11.26,25.33 J9.1@-10.21,26.38
  Top Layer w1: v3@-12.81,40.94 -12.81,41.778 v3@-12.81,43.98
  other v3: -7.82,30.22 -9.93,31.49 -11.23,33.64 -12.353,41.778 -12.407,44.439
IN_GND: J8.5 L6.2 | length 5.9
  Top Layer w0.45: v5(-17.073,44.538) -16.662,44.538 -16.16,45.04 J8.5@-16.16,46.33
  Signal Layer 2 w1.5: v3(-17.609,41.221) -17.073,41.757 v5(-17.073,44.538)
JTAGSEL: "AB RoadRunner.J1-16" J4.11 | length 19
  Top Layer w0.2: v1@-11.447,-2.992 -11.4,-2.992 -10.595,-2.992
  Signal Layer 2 w0.2: J4.11@-28.34,-0.03 -27.94,-0.03 J4.11@-27.78,-0.03 ; -26.54,-1.27 -23.473,-1.27 -23.317,-1.426 -14.114,-1.426 -12.56,-2.98 v1(-11.4,-2.98)
  Signal Layer 2 w0.35: J4.11@-27.78,-0.03 -26.54,-1.27
NC427: J4.27
NC431: J4.31
NC534: J5.34
NC535: J5.35
NC637: J6.37
NetC5_1: C5.1 R3.1 R5.1 U6.5 | length 10.1
  Top Layer w0.3: R5.1@-14.338,17.418 -14.338,17.938 -14.203,18.073 -13.109,18.073 -12.636,17.6 v4(-12.434,17.6) -12.434,16.464 U6.5@-12.43,16.46 ; R3.1@-9.17,19.274 -9.178,19.266 v4(-9.954,19.266) -9.954,20.385 -9.67,20.669 C5.1@-9.159,20.669
  Bottom Layer w0.3: v4@-12.412,17.376 -12.311,17.477 -10.514,19.274 -9.954,19.274 v4@-9.76,19.274
NetC7_1: C7.1 pad.9@-36.2,16.67 R30.2 R33.1 | length 89
  Top Layer w0.3: R33.1@-37.4,17.82 -36.358,17.82
  Top Layer w0.4: -36.27,17.792 -35.08,17.792 R30.2@-35.03,17.792 ; v5(-20.72,28.31) -19.73,28.31 v5(-19.7,28.34) ; C7.1@15.978,48.107 C7.1@16.78,47.305 C7.1@15.982,46.507 ; C7.1@16.806,47.305 v6(17.604,46.507) ; C7.1@16.808,47.305 v6(17.604,48.101)
  Signal Layer 2 w0.4: v4@-36.49,17.388 -36.49,19.45 -35.855,20.085 -35.855,23.962 -34.517,25.3 -34.369,25.3 -34.09,25.579 -27.217,25.579 -26.27,26.526 -22.074,26.526 -20.505,28.095 -20.26,28.34 v5(-19.7,28.34)
  Bottom Layer w0.4: v4(-36.358,17.388) -36.345,17.401 v4(-36.345,18.182) ; v5@-20.72,28.3 -18.85,28.3 -15.39,24.84 -11.92,24.84 -10.96,23.88 -6.45,23.88 -5.83,24.5 -5.83,35.63 -3.86,37.6 7.075,37.6 15.964,46.489 C7.1@16.78,47.305
  other v6: 15.946,46.507 15.978,48.133
NetC19_1: C19.1 U2.5 Y1.1 | length 3.7
  Top Layer w0.2: Y1.1@16.9,30.1 16.9,30.042 17.55,29.392 17.55,29 ; C19.1@17.05,29 17.55,29 ; U2.5@17.55,27.15 17.55,29
NetC20_1: C20.1 U2.4 Y1.3 | length 5.6
  Top Layer w0.2: U2.4@18.05,27.15 18.05,29 ; C20.1@18.55,29 18.05,29 ; Y1.3@18.55,31.77 17.778,30.998 17.778,29.702 18.05,29.43 18.05,29
NetC22_1: C22.1 C23.1 U2.6 | length 6.2
  Top Layer w0.2: C22.1@13.069,28.657 14.833,28.657 15.56,27.93 ; C23.1@14.68,27.19 15.09,27.19 15.56,27.66 15.56,27.93 ; U2.6@17.05,27.15 17.05,27.58 16.7,27.93 15.56,27.93
NetC25_1: C25.1 J2.1 L2.2 | length 13
  Top Layer w0.4: C25.1@-43.18,32.07 -41.57,32.07 L2.2@-41.56,32.08
  Top Layer w0.6: L2.2@-41.56,32.08 -41.61,32.13 -41.61,33.83 -41.96,34.18 -41.96,40.65 -40.38,42.23 J2.1@-39.935,42.23
NetD1_A: D1.A R19.2 U2.15 | length 7.1
  Top Layer w0.2: v2(17.95,21.53) 18.05,21.63 U2.15@18.05,23.25 U2.15@18.05,23.3 ; D1.A@20.68,19.52 v2(20.68,21.54) ; 20.76,20.68 R19.2@21.26,20.68
  Bottom Layer w0.2: v2(17.95,21.53) 20.67,21.53 v2(20.68,21.54)
NetD2_K: D2.K R30.1 | length 1.4
  Top Layer w0.4: R30.1@-33.55,17.785 D2.K@-32.114,17.785
NetDL1_A: DL1.A R8.2 | length 0.8
  Top Layer w0.3: R8.2@27.05,-43.79 27.05,-44.58 DL1.A@27.09,-44.62
NetDL2_A: DL2.A R2.2 | length 1.3
  Top Layer w0.3: R2.2@-3.15,18.7 -1.94,18.7 DL2.A@-1.91,18.67
NetJ1_2: J1.2 Q2.1 R29.2 | length 6.6
  Top Layer w0.2: R29.2@-43.584,24.478 R29.2@-43.584,24.478 -43.583,25.412
  Top Layer w0.3: J1.2@-46.818,25.417 -41.855,25.427
  Top Layer w0.35: -41.855,25.427 -41.247,25.427 Q2.1@-41.2,25.38
NetJ1_3: J1.3 R28.2 | length 3.2
  Top Layer w0.3: J1.3@-46.818,27.957 -43.608,27.957 R28.2@-43.604,27.953
NetJ2_4: J2.4 L5.2 | length 2.4
  Top Layer w0.6: L5.2@-38.29,32.18 J2.4@-38.29,34.61
NetJ7_1: J7.1 L1.2 | length 19.4
  Top Layer w0.5: -24.96,30.95 L1.2@-23.61,30.95
  Top Layer w1.3: v3(-25.45,31.6) -25.45,30.21 v3(-25.43,30.19)
  Bottom Layer w0.8: J7.1@-26.622,41.01 -26.14,41.01 -24.43,39.3 -24.43,38.54 -21.53,35.64 -21.53,32.95 -23.53,30.95 -25.43,30.95 -25.45,30.95 -25.47,30.95
  Bottom Layer w1.3: v3@-25.47,30.2 -25.47,30.95 v3@-25.47,31.59
NetJ7_4: J7.4 L4.2 | length 6.3
  Top Layer w0.6: -28.48,32.32 -28.45,32.29 L4.2@-28.45,30.84
  Top Layer w1.3: v3(-29.16,32.32) -27.77,32.32 v3(-27.75,32.34)
  Bottom Layer w0.8: -28.43,32.34 -28.09,32.68 -26.622,34.148 J7.4@-26.622,35.01
NetJ10_3: J10.3 R31.1 | length 3.6
  Top Layer w0.22: R31.1@3.6,23.45 3.6,24.7 4.2,25.3 J10.3@4.2,26.81
NetJ10_4: J10.4 R32.1 | length 3.4
  Top Layer w0.22: R32.1@1.7,23.45 J10.4@1.7,26.81
NetL7_1: L7.1 U6.3 | length 4.9
  Top Layer w0.7: U6.3@-10.53,14.114 -10.53,13.33 -10.096,12.896 -8.079,12.896 -7.614,13.361 L7.1@-7.614,14.223
NetP1_2: P1.2 R27.1 | length 3.3
  Top Layer w0.25: 24.961,-44.71 R27.1@24.961,-44.183
  Top Layer w0.3: P1.2@22.28,-44.88 24.791,-44.88 24.961,-44.71
NetP2_2: P2.2 R34.1 | length 5.4
  Top Layer w0.3: R34.1@-35.83,-40.58 -35.81,-40.6 -35.14,-40.6
  Top Layer w0.4: -35.14,-40.6 -34.42,-41.32 -34.42,-43.05 -33.99,-43.48 P2.2@-32.6,-43.48
NetQ2_3: Q2.3 Q3.1 R1.2 | length 6.7
  Top Layer w0.3: Q2.3@-39.27,24.43 -39.2,24.36 -39.145,24.305 -39.13,24.305 Q3.1@-37.304,24.305 ; R1.2@-38.691,27.955 -37.94,27.955 -37.304,27.319 Q3.1@-37.304,24.305 ; Q3.1@-37.302,24.303 Q3.1@-37.304,24.305
NetR20_1: R20.1 U2.3 | length 6.2
  Top Layer w0.2: U2.3@18.55,27.15 18.55,27.75 19.111,28.311 19.721,28.311 20.31,28.9 21.095,28.9 21.52,29.325 21.52,30.5 21.65,30.63 R20.1@22.02,30.63 22.03,30.63 R20.1@22.2,30.46
NetR21_1: R21.1 R22.2 U2.2 | length 6.1
  Top Layer w0.2: U2.2@19.05,27.15 19.05,27.657 19.323,27.93 19.908,27.93 20.413,28.435 21.225,28.435 21.82,29.03 ; R21.1@22.46,29.64 22.08,29.64 21.93,29.49 21.93,29.14 21.82,29.03 ; R22.2@22.7,28.47 22.68,28.47 22.38,28.47 21.82,29.03
NetR23_1: R23.1 U2.24 | length 5.5
  Top Layer w0.2: U2.24@20.25,26.45 21.52,26.45 22.12,27.05 24.74,27.05 24.96,27.27 R23.1@25.39,27.27
NRST: "AB RoadRunner.J1-24" D1.K J5.37 R27.2 | length 112.3
  Top Layer w0.2: v1(-12.015,-4.146) -12.036,-4.146 -12.05,-4.16 -12.04,-4.17 -11.617,-4.593 -10.595,-4.593
  Top Layer w0.25: D1.K@20.67,18.12 20.67,17.19 v2(20.68,17.18) ; v1(21.751,-33.135) 23.37,-33.135 J5.37@23.485,-33.02 ; v1(21.805,-42.231) 24.46,-42.231 24.961,-42.732 R27.2@24.961,-43.283
  Signal Layer 2 w0.25: v1(-12.015,-4.146) -12.036,-4.146 -12.05,-4.16 -12.04,-4.17 -11.82,-4.39 -11.722,-4.39 -11.693,-4.361 -10.887,-4.361 -10.858,-4.39 -10.66,-4.39 -10.326,-4.056 -8.908,-4.056 ; v2(20.68,17.18) 20.68,16.29 21.27,15.7 21.27,14.276 18.284,11.29 18.284,10.625 15.43,7.771 15.43,5.24 14.35,4.16 2.76,4.16 -5.456,-4.056 -8.908,-4.056 ; v1(21.751,-33.135) v1@21.751,-33.212 ; v1(21.805,-42.231) 21.805,-40.145 22.725,-39.225 22.725,-34.186 v1@21.751,-33.212 ; -8.908,-4.056 -3.796,-9.168 -3.796,-15.444 10.48,-29.72 10.48,-31.477 12.699,-33.696 21.267,-33.696 v1@21.751,-33.212
PA0: "AB RoadRunner.J1-49" J4.20 | length 12.3
  Top Layer w0.2: J4.20@-25.4,-10.16 -24.1,-10.16 J4.20@-23.485,-10.16 -19.936,-10.16 -19.08,-9.304 -15.865,-9.304 -15.377,-9.793 -13.705,-9.793
PA1: "AB RoadRunner.J1-68" J3.28 | length 35.8
  Top Layer w0.2: -10.595,-13.393 -9.8,-13.393 v1@-9.669,-13.523
  Signal Layer 2 w0.2: -33.74,-20.32 -32.45,-21.61 -21.29,-21.61 -14.64,-14.96 -12.54,-14.96 -12.021,-14.441 -10.785,-14.441 -9.926,-13.582 v1(-9.636,-13.582)
  Signal Layer 2 w0.35: J3.28@-40.619,-20.32 -33.74,-20.32
PA2: "AB RoadRunner.J1-58" J3.20 | length 31.8
  Top Layer w0.2: v1@-11.447,-11.392 -11.37,-11.392 -10.595,-11.392
  Signal Layer 2 w0.2: -35.33,-10.16 -34.055,-11.435 -23.61,-11.435 -22.415,-10.24 -20.179,-10.24 -19.669,-10.75 -14.776,-10.75 -14.506,-10.48 -12.265,-10.48 v1@-11.382,-11.362
  Signal Layer 2 w0.35: J3.20@-40.648,-10.16 J3.20@-40.64,-10.16 -35.33,-10.16
  other v1: -11.37,-11.35
PA3: "AB RoadRunner.J1-64" J3.24 | length 34.7
  Top Layer w0.2: -10.595,-12.592 -9.773,-12.592 v1(-9.526,-12.346)
  Signal Layer 2 w0.2: -33.76,-15.24 -32.51,-16.49 -19.36,-16.49 -15.33,-12.46 -12.6,-12.46 -12.37,-12.69 -11.932,-12.69 -11.672,-12.43 -10.39,-12.43 -10.306,-12.346 v1(-9.526,-12.346)
  Signal Layer 2 w0.35: J3.24@-40.629,-15.24 -33.76,-15.24
PA4: "AB RoadRunner.J1-60" J3.22 | length 35.2
  Top Layer w0.2: -10.595,-11.792 -9.916,-11.792 -9.82,-11.696 v1(-8.858,-11.696)
  Signal Layer 2 w0.2: -35.38,-12.78 -34.19,-13.97 -20.83,-13.97 -18.93,-12.07 -13.106,-12.07 -12.626,-11.59 -11.88,-11.59 -11.59,-11.88 -10.383,-11.88 -10.199,-11.696 v1(-8.858,-11.696)
  Signal Layer 2 w0.35: J3.22@-40.649,-12.78 -40.64,-12.78 -35.38,-12.78
PA5: "AB RoadRunner.J1-62" J4.25 | length 23.6
  Top Layer w0.2: v1@-12.07,-12.193 -10.595,-12.193
  Bottom Layer w0.2: -26.59,-16.5 -22.9,-16.5 -20.95,-14.55 -11.72,-14.55 -11.62,-14.45 -10.9,-14.45 -10.63,-14.18 -10.63,-12.57 -11.08,-12.12 v1(-12.19,-12.12)
  Bottom Layer w0.35: J4.25@-27.905,-17.815 -26.59,-16.5
PA6: "AB RoadRunner.J1-67" J4.30 | length 18.2
  Top Layer w0.2: J4.30@-25.4,-22.87 -23.485,-22.87 -21.3,-22.87 -19.19,-20.76 -19.19,-16.3 -16.282,-13.393 -13.705,-13.393
PA7: "AB RoadRunner.J1-66" J3.21 | length 34
  Top Layer w0.2: v1@-11.447,-12.992 -11.331,-12.992 -10.595,-12.992
  Bottom Layer w0.2: -41.92,-11.44 -21.61,-11.44 -21.5,-11.33 -19.21,-11.33 -18.17,-12.37 -12.73,-12.37 -12.12,-12.98 v1(-11.331,-12.98)
  Bottom Layer w0.35: J3.21@-43.18,-12.7 -41.92,-11.44
PA8: "AB RoadRunner.J1-71" J4.32 | length 20.2
  Top Layer w0.2: J4.32@-25.4,-25.42 -23.485,-25.42 -20.24,-25.42 -18.358,-23.538 -18.358,-17.037 -15.514,-14.192 -13.705,-14.192
PA9: "AB RoadRunner.J1-73" J4.33 | length 23.9
  Top Layer w0.2: -26.671,-26.671 -20.331,-26.671 -19.4,-25.74 -19.4,-25.2 -17.978,-23.778 -17.978,-17.194 -15.376,-14.593 -13.705,-14.593
  Top Layer w0.35: J4.33@-27.94,-27.94 -26.671,-26.671
PA10: "AB RoadRunner.J1-70" J3.26 | length 32.8
  Top Layer w0.2: v1(-12.083,-13.897) -11.979,-13.792 -10.595,-13.792
  Signal Layer 2 w0.2: -34.62,-17.78 -33.36,-19.04 -19.45,-19.04 -14.97,-14.56 -12.746,-14.56 v1(-12.083,-13.897)
  Signal Layer 2 w0.35: J3.26@-40.655,-17.78 J3.26@-40.64,-17.78 -34.62,-17.78
PA11: "AB RoadRunner.J1-75" J4.34 | length 21.9
  Top Layer w0.2: J4.34@-25.4,-27.97 -23.485,-27.97 -20.01,-27.97 -18.99,-26.95 -18.99,-25.38 -17.598,-23.988 -17.598,-17.351 -15.239,-14.992 -13.705,-14.992
PA12: "AB RoadRunner.J1-77" J4.35 | length 26.3
  Top Layer w0.2: J4.35@-27.95,-30.72 -27.95,-30.5 J4.35@-27.935,-30.485 ; -26.66,-29.21 -19.42,-29.21 -18.58,-28.37 -18.58,-25.58 -17.218,-24.218 -17.218,-17.509 -15.102,-15.392 -13.705,-15.392
  Top Layer w0.35: J4.35@-27.935,-30.485 -26.66,-29.21
PA13: "AB RoadRunner.J1-79" J4.36 | length 23.9
  Top Layer w0.2: J4.36@-25.4,-30.48 -24.1,-30.48 J4.36@-23.485,-30.48 -19.14,-30.48 -18.16,-29.5 -18.16,-25.74 -16.838,-24.418 -16.838,-17.666 -14.964,-15.793 -13.705,-15.793
PA14: "AB RoadRunner.J1-91" J3.31 | length 53.8
  Top Layer w0.2: -41.956,-26.67 -35.19,-26.67 -34.26,-27.6 -34.26,-34.01 -30.69,-37.58 -21.36,-37.58 -16.58,-32.8 -16.58,-26.68 -15.318,-25.418 -15.318,-18.75 -14.76,-18.192 -14.727,-18.192 -14.71,-18.21 -13.722,-18.21 -13.705,-18.192
  Top Layer w0.35: J3.31@-43.203,-25.423 -41.956,-26.67
PA15: "AB RoadRunner.J1-76" J3.33 | length 43.3
  Top Layer w0.2: v1@-11.447,-14.992 -11.4,-14.992 -10.595,-14.992
  Signal Layer 2 w0.2: -42.023,-29.211 -36.769,-29.211 -36.43,-29.55 -35.53,-29.55 -35.191,-29.211 -21.421,-29.211 -21.06,-28.85 -21.06,-22.07 -14.37,-15.38 -12.367,-15.38 -11.967,-14.98 v1(-11.4,-14.98)
  Signal Layer 2 w0.35: J3.33@-43.24,-28 -42.029,-29.211
PA16: "AB RoadRunner.J1-81" J4.37 | length 28.2
  Top Layer w0.2: -26.67,-31.75 -18.36,-31.75 -17.72,-31.11 -17.72,-25.95 -16.458,-24.688 -16.458,-17.824 -14.827,-16.192 -13.705,-16.192
  Top Layer w0.35: J4.37@-27.94,-33.02 -26.67,-31.75
PA17: "AB RoadRunner.J1-83" J4.38 | length 26.1
  Top Layer w0.2: J4.38@-25.4,-33.04 -23.485,-33.04 -18.14,-33.04 -17.34,-32.24 -17.34,-26.22 -16.078,-24.958 -16.078,-17.981 -14.689,-16.592 -13.705,-16.592
PA18: "AB RoadRunner.J1-74" U1.2 | length 21
  Top Layer w0.2: -10.595,-14.593 v2@-7.46,-14.593 ; v2(-7.46,-17.74) -2.65,-22.55 U1.2@-2.65,-30.43
  Bottom Layer w0.2: v2(-7.46,-17.74) v2(-7.46,-14.56)
PA19: "AB RoadRunner.J1-78" U1.1 | length 22.5
  Top Layer w0.2: -10.587,-15.4 -10.137,-15.4 ; -10.145,-15.392 -10.137,-15.4 ; U1.1@-2.25,-30.43 -2.25,-18.59 -2.673,-18.167 -4.533,-18.167 -5.018,-17.682 -5.018,-16.072 -5.69,-15.4 -10.137,-15.4
PA20: "AB RoadRunner.J1-72" U1.8 | length 21
  Top Layer w0.2: -10.595,-14.192 -9.142,-14.192 -8.93,-13.98 v2(-8.59,-13.98) ; v2(-8.95,-25.94) -7.975,-26.915 -7.975,-28.075 -7.185,-28.865 -6.025,-28.865 -5.05,-29.84 U1.8@-5.05,-30.43
  Bottom Layer w0.2: v2(-8.95,-25.94) -8.95,-24.65 -8.76,-24.46 -8.76,-14.15 v2(-8.59,-13.98)
PA21: "AB RoadRunner.J1-87" U1.7 | length 18.4
  Top Layer w0.2: -13.705,-17.393 -13.242,-17.393 -13.102,-17.253 -12.422,-17.253 v2(-12.14,-17.535) ; v2(-11.53,-21.68) -11.53,-23.41 -11.27,-23.67 -10.09,-23.67 -4.65,-29.11 U1.7@-4.65,-30.43
  Bottom Layer w0.2: v2(-12.14,-17.535) -12.14,-21.07 v2(-11.53,-21.68)
PA22: "AB RoadRunner.J1-95" R24.1 | length 6.8
  Top Layer w0.2: v2@-14.61,-18.992 -13.705,-18.992 -13.277,-18.992 -13.074,-19.196 -12.604,-19.196 -12.3,-19.5 -12.3,-20.07 -10.93,-21.44 -10.93,-22.27 -10.71,-22.49 R24.1@-10.29,-22.49
  Bottom Layer w0.2: v2(-14.61,-18.99) -14.61,-18.981 v2@-14.475,-18.846
PA23: "AB RoadRunner.J1-92" J3.30 | length 67.3
  Top Layer w0.2: -10.595,-18.192 -9.79,-18.192 v1@-9.742,-18.192
  Signal Layer 2 w0.2: -41.62,-23.66 -41.636,-23.66 -42.127,-23.66 -42.607,-24.14 -43.68,-24.14 -44.62,-25.08 -44.62,-36.115 -42.395,-38.34 -22.11,-38.34 -18.19,-34.42 -18.19,-26.79 -15.28,-23.88 -12.15,-23.88 -10.447,-22.177 -10.447,-18.837 v1(-9.79,-18.18)
  Signal Layer 2 w0.35: -41.637,-23.661 -41.636,-23.66 -40.828,-22.852 J3.30@-40.65,-22.852
PA24: "AB RoadRunner.J1-90" J3.34 | length 38.8
  Top Layer w0.2: v1@-11.447,-17.792 -10.595,-17.792
  Bottom Layer w0.2: -38.714,-27.944 -33.826,-27.944 -32.559,-29.211 -21.421,-29.211 -19.65,-27.44 -19.65,-22.96 -14.95,-18.26 -14.12,-18.26 -12.81,-16.95 -11.905,-16.95 -11.45,-17.405 v1(-11.45,-17.79)
  Bottom Layer w0.35: J3.34@-40.64,-27.944 -38.714,-27.944
PA25: "AB RoadRunner.J1-94" J3.38 | length 45
  Top Layer w0.2: v1@-11.447,-18.593 -10.595,-18.593
  Signal Layer 2 w0.2: J3.38@-40.633,-33.02 -36.74,-33.02 -32.31,-37.45 -22.57,-37.45 -18.99,-33.87 -18.99,-26.34 -15.52,-22.87 -14.52,-22.87 -12.224,-20.574 -12.224,-19.814 -11.98,-19.57 -11.98,-18.827 -11.768,-18.615 -11.45,-18.615 v1@-11.425,-18.615
  other v1: -11.45,-18.59
PA26: "AB RoadRunner.J1-96" J3.23 | length 75.6
  Top Layer w0.2: -10.595,-18.992 -9.79,-18.992 v1@-9.742,-18.992
  Signal Layer 2 w0.2: -45.115,-15.712 -44.643,-15.24 ; -45.11,-15.712 -45.11,-36.427 -42.757,-38.78 -21.91,-38.78 -17.81,-34.68 -17.81,-27.11 -15.055,-24.355 -11.885,-24.355 -10,-22.47 -10,-20.948 -8.856,-19.804 -8.856,-19.502 -9.378,-18.98 v1(-9.79,-18.98)
  Signal Layer 2 w0.35: -44.643,-15.24 J3.23@-43.18,-15.24
PA27: "AB RoadRunner.J1-88" J3.35 | length 49.3
  Top Layer w0.2: -10.595,-17.393 -9.79,-17.393 v1@-9.742,-17.393
  Signal Layer 2 w0.2: -41.924,-31.74 -41.91,-31.74 -36.658,-31.74 -35.818,-32.58 -35.14,-32.58 -33.41,-34.31 -20.68,-34.31 -20.17,-33.8 -20.17,-23.445 -15.005,-18.28 -14.21,-18.28 -12.83,-16.9 -10.82,-16.9 -10.34,-17.38 v1(-9.79,-17.38)
  Signal Layer 2 w0.35: J3.35@-43.175,-30.475 -41.91,-31.74
PA28: "AB RoadRunner.J1-80" U1.6 | length 21
  Top Layer w0.2: -10.595,-15.793 -8.797,-15.793 v2(-8.16,-16.43) ; v2(-7.99,-24.71) -7.055,-25.645 -5.895,-25.645 -5.185,-26.355 -5.185,-27.515 -4.25,-28.45 U1.6@-4.25,-30.43
  Bottom Layer w0.2: v2(-8.16,-16.43) -8.16,-18.457 -7.87,-18.747 -7.483,-18.747 -7.29,-18.94 -7.29,-19.327 -7,-19.617 -7,-20.051 -7.33,-20.381 -7.33,-20.589 -7,-20.919 -7,-21.353 -7.29,-21.643 -7.29,-22.03 -7.483,-22.223 -7.87,-22.223 -8.16,-22.513 -8.16,-23.019 -7.81,-23.369 -7.81,-23.683 -8.16,-24.033 -8.16,-24.54 v2(-7.99,-24.71)
PA29: "AB RoadRunner.J1-82" J3.25 | length 37.1
  Top Layer w0.2: v1@-11.447,-16.192 -10.595,-16.192
  Bottom Layer w0.2: -41.91,-19.05 -36.31,-19.05 -33.74,-21.62 -20.49,-21.62 -14.19,-15.32 -12.43,-15.32 -11.7,-16.05 v1(-11.45,-16.05)
  Bottom Layer w0.35: J3.25@-43.18,-17.78 -41.91,-19.05
PA30: "AB RoadRunner.J1-84" J3.27 | length 39
  Top Layer w0.2: -10.595,-16.592 -9.79,-16.592 v1@-9.742,-16.592
  Bottom Layer w0.2: -41.9,-21.6 -38.56,-21.6 -37.44,-22.72 -34.47,-22.72 -33.13,-24.06 -23.71,-24.06 -23.1,-23.45 -21.75,-23.45 -14.79,-16.49 -11.78,-16.49 -11.61,-16.66 -11,-16.66 -10.92,-16.58 v1(-9.79,-16.58)
  Bottom Layer w0.35: J3.27@-43.18,-20.32 -41.9,-21.6
PA31: "AB RoadRunner.J1-86" J3.36 | length 42.7
  Top Layer w0.2: v1(-12.71,-15.91) -12.71,-15.954 -11.672,-16.993 -10.6,-16.993
  Signal Layer 2 w0.2: J3.36@-40.648,-30.48 J3.36@-40.64,-30.48 -35.21,-30.48 -33.95,-31.74 -21.43,-31.74 -20.59,-30.9 -20.59,-22.25 -14.25,-15.91 v1(-12.71,-15.91)
PB0: "AB RoadRunner.J1-85" J3.32 | length 45.9
  Top Layer w0.2: J3.32@-38.1,-25.4 -34.96,-25.4 -33.41,-26.95 -33.41,-32.18 -31.29,-34.3 -18.83,-34.3 -16.96,-32.43 -16.96,-26.45 -15.698,-25.188 -15.698,-18.138 -14.552,-16.993 -13.705,-16.993
PB1: "AB RoadRunner.J2-51" J5.12 | length 27.2
  Top Layer w0.2: 10.595,-10.193 v2@11.238,-10.193
  Bottom Layer w0.2: v2(11.38,-10.05) 11.52,-10.05 11.77,-10.3 18.371,-10.3 21.898,-6.773 21.898,-0.362 22.79,0.53 24.04,0.53 24.79,1.28 26,1.28 26.47,1.75 26.91,1.75 27.94,0.72 J5.12@27.94,0
PB2: "AB RoadRunner.J2-45" J5.9 | length 27.6
  Top Layer w0.2: v2(9.35,-8.91) 9.432,-8.992 10.595,-8.992
  Bottom Layer w0.2: v2(9.35,-8.91) 10.32,-8.91 10.656,-9.246 11.609,-9.246 12.233,-9.87 18.237,-9.87 21.499,-6.608 21.499,1.493 22.546,2.54 J5.9@25.4,2.54
PB3: "AB RoadRunner.J2-43" J5.7 | length 26.9
  Top Layer w0.2: 10.788,-8.592 10.595,-8.592 11.238,-8.592 v2(11.38,-8.45)
  Bottom Layer w0.2: v2(11.38,-8.45) 11.41,-8.45 11.59,-8.63 17.42,-8.63 17.421,-8.629 18.349,-8.629 20.701,-6.277 20.701,4.186 21.595,5.08 J5.7@25.4,5.08
PB4: "AB RoadRunner.J2-38" J5.5 | length 25.1
  Top Layer w0.2: 13.705,-7.392 19.392,-7.392 ; 19.392,-7.391 21.273,-5.51 21.273,6.883 21.94,7.55 23.485,7.55 J5.5@25.4,7.55
PB5: "AB RoadRunner.J2-47" J5.8 | length 28.2
  Top Layer w0.2: 10.595,-9.393 11.045,-9.392 11.238,-9.392 11.36,-9.27 v2(12.73,-9.27)
  Bottom Layer w0.2: v2(12.73,-9.27) 18.272,-9.27 21.1,-6.442 21.1,1.9 22.209,3.009 23.769,3.009 24.571,3.811 26.031,3.811 ; J5.8@27.315,5.095 J5.8@27.925,5.095
  Bottom Layer w0.35: 26.031,3.811 J5.8@27.315,5.095
PB6: "AB RoadRunner.J2-41" J6.12 | length 50.3
  Top Layer w0.2: v2(9.35,-8.11) 9.432,-8.193 10.595,-8.193
  Bottom Layer w0.2: v2(9.35,-8.11) 9.827,-8.11 10.145,-7.793 11.757,-7.793 12.194,-8.23 18.184,-8.23 20.302,-6.112 20.302,4.522 21.4,5.62 24.02,5.62 24.74,6.34 28.98,6.34 34.05,1.27 41.894,1.27
  Bottom Layer w0.35: 41.894,1.27 J6.12@43.172,-0.008
PB7: "AB RoadRunner.J2-37" J6.10 | length 55.7
  Top Layer w0.2: v2(8.96,-7.39) 8.962,-7.392 10.525,-7.392
  Bottom Layer w0.2: v2(8.96,-7.39) 9.747,-7.39 10.849,-6.288 11.923,-6.288 12.242,-5.969 18.041,-5.969 19.47,-4.54 19.47,9.82 20.45,10.8 24.18,10.8 24.82,11.44 28.9,11.44 36.54,3.8 41.907,3.8
  Bottom Layer w0.35: 41.907,3.8 J6.10@43.174,2.534
PB8: "AB RoadRunner.J2-39" J6.9 | length 47.6
  Top Layer w0.2: 10.595,-7.793 11.045,-7.793 12.438,-7.792 v2(12.66,-7.57)
  Bottom Layer w0.2: v2(12.66,-7.57) 12.679,-7.551 18.299,-7.551 19.903,-5.947 19.903,7.683 20.52,8.3 24.21,8.3 24.82,8.91 28.44,8.91 30.13,7.22 30.545,6.805 31.415,6.805 35.694,2.526 38.37,2.526
  Bottom Layer w0.35: 38.37,2.54 J6.9@40.64,2.54
PB9: "AB RoadRunner.J2-35" J6.11 | length 46.4
  Top Layer w0.2: v2(8.644,-6.46) 9.14,-6.46 9.673,-6.993 10.595,-6.993
  Signal Layer 2 w0.2: v2(8.644,-6.46) 8.963,-6.779 10.361,-6.779 10.8,-6.34 11.825,-6.34 12.214,-5.951 18.117,-5.951 18.458,-5.61 19.158,-5.61 20.28,-4.488 20.28,2.36 24.28,6.36 29.31,6.36 35.676,-0.006 38.289,-0.006
  Signal Layer 2 w0.35: 38.289,-0.006 J6.11@40.64,-0.006
PB10: "AB RoadRunner.J2-73" J6.14 | length 49.6
  Top Layer w0.2: v2(9.35,-14.51) 9.432,-14.593 10.595,-14.593
  Signal Layer 2 w0.2: v2(9.35,-14.51) 9.92,-14.51 10.255,-14.845 11.455,-14.845 11.941,-14.359 12.986,-14.359 13.165,-14.18 16.29,-14.18 24.17,-6.3 24.17,-4.57 24.92,-3.82 25.97,-3.82 26.43,-3.36 26.89,-3.36 27.35,-3.82 31.86,-3.82 34.391,-6.351 43.799,-6.351 45.73,-4.42 45.73,-3.21 45.075,-2.555
  Signal Layer 2 w0.35: J6.14@43.18,-2.555 45.075,-2.555
PB11: "AB RoadRunner.J2-32" J5.3 | length 26.6
  Top Layer w0.2: 13.705,-6.192 17.608,-6.192 17.936,-5.864 19.273,-5.864 20.455,-4.682 20.455,9.115 21.51,10.17 23.485,10.17 J5.3@25.4,10.17
PB12: "AB RoadRunner.J2-36" J5.6 | length 29.3
  Top Layer w0.2: 13.705,-6.993 19.088,-6.993 ; 19.088,-6.991 20.864,-5.215 20.864,7.904 21.491,8.531 24.401,8.531 24.78,8.91 27.005,8.91 ; J5.6@27.915,7.595 27.915,7.62 J5.6@27.915,7.999
  Top Layer w0.35: 27.005,8.91 J5.6@27.915,7.999
PB13: "AB RoadRunner.J2-30" J5.2 | length 30.4
  Top Layer w0.2: 13.705,-5.793 17.296,-5.793 17.659,-5.429 18.899,-5.429 20.029,-4.299 20.029,10.049 21.079,11.099 24.219,11.099 24.552,11.432 26.862,11.432 J5.2@28.035,12.605
PB24: "AB RoadRunner.J1-15" J4.8 | length 12.4
  Top Layer w0.2: J4.8@-22.73,4.71 -22.73,4.563 -21.96,3.793 -21.96,3.578 -15.39,-2.992 -13.705,-2.992
PB25: "AB RoadRunner.J1-13" J4.7 | length 19.4
  Top Layer w0.2: -26.67,6.35 -22.53,6.35 -21.544,5.364 -21.544,3.726 -15.225,-2.592 -13.705,-2.592
  Top Layer w0.35: J4.7@-27.94,5.08 -26.67,6.35
PB26: "AB RoadRunner.J1-11" J4.6 | length 16.7
  Top Layer w0.2: J4.6@-25.4,7.62 -24.1,7.62 J4.6@-23.485,7.62 -23.21,7.62 -21.145,5.555 -21.145,3.891 -15.061,-2.193 -13.705,-2.193
PB27: "AB RoadRunner.J1-9" J4.5 | length 21
  Top Layer w0.2: -26.67,8.89 -22.39,8.89 -20.72,7.22 -20.72,4.15 -14.777,-1.793 -13.705,-1.793
  Top Layer w0.35: J4.5@-27.94,7.62 -26.67,8.89
PB28: "AB RoadRunner.J1-7" J4.4 | length 18.3
  Top Layer w0.2: J4.4@-25.4,10.16 -24.1,10.16 J4.4@-23.485,10.16 -23.05,10.16 -20.34,7.45 -20.34,4.308 -14.64,-1.392 -13.705,-1.392
PB29: "AB RoadRunner.J1-5" J4.3 | length 22.5
  Top Layer w0.2: -26.68,11.42 -22.48,11.42 -19.96,8.9 -19.96,4.465 -14.502,-0.992 -13.705,-0.992
  Top Layer w0.35: J4.3@-27.94,10.16 -26.68,11.42
PB30: "AB RoadRunner.J1-3" J4.2 | length 18.6
  Top Layer w0.2: J4.2@-24.1,12.7 J4.2@-23.485,12.7 -23.09,12.7 -19.58,9.19 -19.58,4.623 -14.365,-0.593 -13.705,-0.593
PB31: "AB RoadRunner.J1-1" J4.1 | length 24.8
  Top Layer w0.2: -25.66,14.94 -23.66,14.94 -19.2,10.48 -19.2,4.78 -14.228,-0.192 -13.705,-0.192
  Top Layer w0.35: J4.1@-27.92,12.68 -25.66,14.94
PC0: "AB RoadRunner.J1-63" J4.28 | length 16.6
  Top Layer w0.2: J4.28@-25.4,-20.34 -23.485,-20.34 -20.95,-20.34 -19.59,-18.98 -19.59,-16.15 -16.44,-13 -14.65,-13 -14.242,-12.592 -13.705,-12.592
